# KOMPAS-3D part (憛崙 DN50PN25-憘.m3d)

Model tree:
1. Объединить компоненты:1  (labels: СЕНС DN50PN25)
2. Эскиз:1
3. Операция выдавливания:1
     Расстояние 1 = 14
4. Фаска:1
     Угол = 45; Длина 1 = 2; Длина 2 = 2

Referenced files in D:\Савин\!СЕНСОР\3D для заказчика\!Новый перечень\СЕНС\1. СЕНС\DN50\: СЕНС DN50PN25.a3d
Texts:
  СЕНС DN50PN25-СВ
  СЕНС DN50PN25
